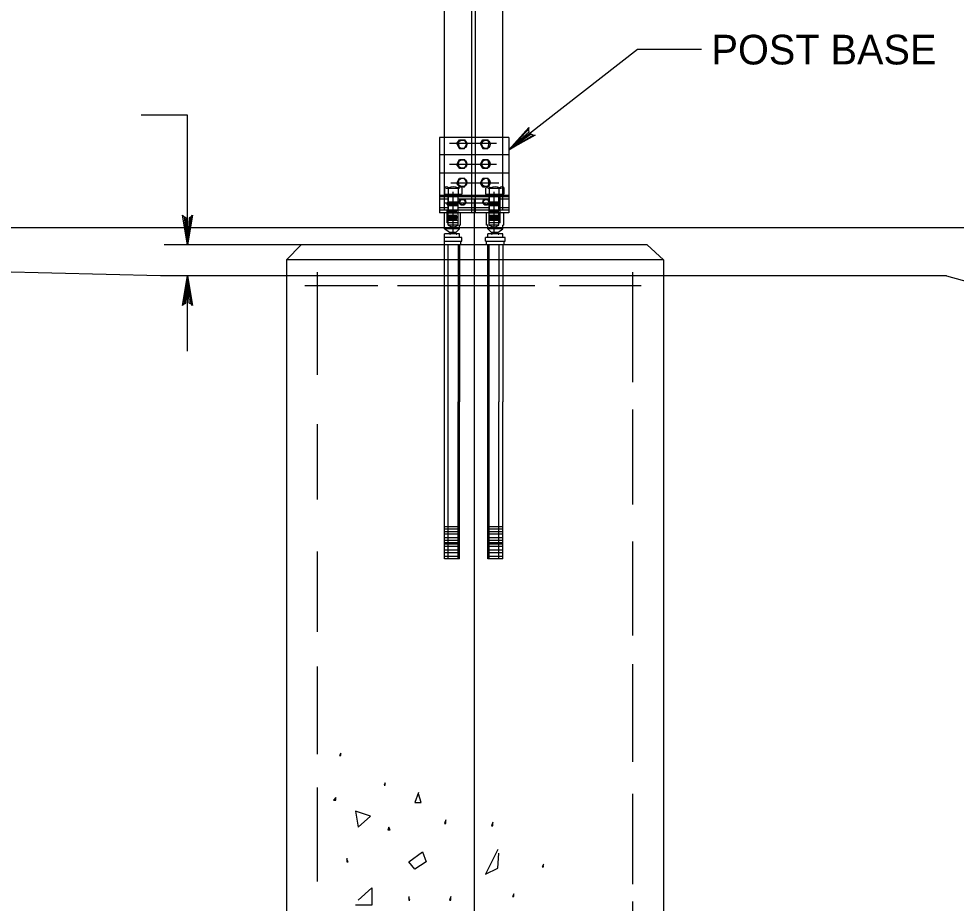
# Model space of a CAD drawing. Extents: x 637580 to 641008, y 294594 to 295782.
# Drawn here: x 637895.1 to 637989.9, y 295392.1 to 295481.5 of the extents above; entities that cross this region are included whole.
import ezdxf

# ---------------------------------------------------------------- set-up
doc = ezdxf.new("R2010")
doc.units = 0
for name, color, linetype in [('1', 7, 'Continuous'), ('2', 7, 'Continuous'), ('3', 7, 'Continuous')]:
    doc.layers.add(name, color=color, linetype=linetype)

# ---------------------------------------------------------------- blocks, each defined once
blk = doc.blocks.new('RARROW')
at = {"layer": '3'}
blk.add_lwpolyline([(-2.2695, 0.285), (-2.184875, 0.12075), (0, 0), (-2.2695, 0.285), (-2.38575, 0.384625), (0, 0), (-2.183125, -0.108), (-2.262875, -0.2705), (0, 0), (-2.38575, -0.379125), (-2.262875, -0.2705)], dxfattribs=at)

msp = doc.modelspace()

# ---------------------------------------------------------------- linework, layer by layer
at = {"layer": '2'}
for p, q in [((637940.937, 295461.876), (637940.937, 295676.876)), ((637941.312, 295461.876), (637941.312, 295676.876)), ((637938.187, 295469.501), (637938.187, 295549.501)), ((637944.062, 295469.501), (637944.062, 295549.501)), ((637957.687, 295478.376), (637944.687, 295468.236)), ((637964.187, 295478.376), (637957.687, 295478.376)), ((637912.187, 295471.751), (637907.499, 295471.751)), ((637912.187, 295458.626), (637912.187, 295471.751)), ((637944.687, 295469.501), (637937.687, 295469.501)), ((637937.687, 295469.501), (637937.687, 295462.126)), ((637938.187, 295462.126), (637938.187, 295469.501)), ((637939.437, 295468.876), (637939.687, 295469.251)), ((637939.562, 295468.876), (637939.687, 295469.251)), ((637939.687, 295469.251), (637940.187, 295469.251)), ((637939.687, 295469.251), (637940.187, 295469.251)), ((637940.187, 295469.251), (637940.437, 295468.876)), ((637940.437, 295468.876), (637940.187, 295469.251)), ((637941.812, 295468.876), (637942.062, 295469.251)), ((637941.812, 295468.876), (637942.062, 295469.251)), ((637942.062, 295469.251), (637942.562, 295469.251)), ((637942.062, 295469.251), (637942.562, 295469.251)), ((637942.562, 295469.251), (637942.687, 295468.876)), ((637942.687, 295468.876), (637942.562, 295469.251)), ((637944.062, 295462.126), (637944.062, 295469.501)), ((637944.687, 295469.501), (637944.687, 295462.126)), ((637943.437, 295468.876), (637938.687, 295468.876)), ((637939.687, 295468.376), (637939.437, 295468.876)), ((637939.562, 295468.876), (637939.687, 295468.376)), ((637939.687, 295468.376), (637940.187, 295468.376)), ((637939.687, 295468.376), (637940.187, 295468.376)), ((637939.937, 295468.876), (637939.937, 295468.876)), ((637939.937, 295468.876), (637939.937, 295468.876)), ((637939.937, 295468.876), (637939.937, 295468.876)), ((637940.187, 295468.376), (637940.437, 295468.876)), ((637940.187, 295468.376), (637940.437, 295468.876)), ((637941.812, 295468.876), (637942.062, 295468.376)), ((637942.062, 295468.376), (637941.812, 295468.876)), ((637942.062, 295468.376), (637942.562, 295468.376)), ((637942.062, 295468.376), (637942.562, 295468.376)), ((637942.312, 295468.876), (637942.312, 295468.876)), ((637942.312, 295468.876), (637942.312, 295468.876)), ((637942.312, 295468.876), (637942.312, 295468.876)), ((637942.562, 295468.376), (637942.687, 295468.876)), ((637942.562, 295468.376), (637942.687, 295468.876)), ((637944.687, 295467.751), (637937.687, 295467.751)), ((637943.437, 295466.751), (637938.687, 295466.751)), ((637939.437, 295466.751), (637939.687, 295467.251)), ((637939.687, 295466.376), (637939.437, 295466.751)), ((637939.562, 295466.751), (637939.687, 295467.251)), ((637939.562, 295466.751), (637939.687, 295466.376)), ((637939.687, 295467.251), (637940.187, 295467.251)), ((637939.687, 295467.251), (637940.187, 295467.251)), ((637939.937, 295466.751), (637939.937, 295466.751)), ((637939.937, 295466.751), (637939.937, 295466.751)), ((637939.937, 295466.751), (637939.937, 295466.751)), ((637940.187, 295467.251), (637940.437, 295466.751)), ((637940.437, 295466.751), (637940.187, 295467.251)), ((637940.187, 295466.376), (637940.437, 295466.751)), ((637940.187, 295466.376), (637940.437, 295466.751)), ((637941.812, 295466.751), (637942.062, 295467.251)), ((637941.812, 295466.751), (637942.062, 295467.251)), ((637941.812, 295466.751), (637942.062, 295466.376)), ((637942.062, 295466.376), (637941.812, 295466.751)), ((637942.062, 295467.251), (637942.562, 295467.251)), ((637942.062, 295467.251), (637942.562, 295467.251)), ((637942.312, 295466.751), (637942.312, 295466.751)), ((637942.312, 295466.751), (637942.312, 295466.751)), ((637942.312, 295466.751), (637942.312, 295466.751)), ((637942.562, 295467.251), (637942.687, 295466.751)), ((637942.687, 295466.751), (637942.562, 295467.251)), ((637942.562, 295466.376), (637942.687, 295466.751)), ((637942.562, 295466.376), (637942.687, 295466.751)), ((637944.687, 295465.876), (637937.687, 295465.876)), ((637939.687, 295466.376), (637940.187, 295466.376)), ((637939.687, 295466.376), (637940.187, 295466.376)), ((637942.062, 295466.376), (637942.562, 295466.376)), ((637942.062, 295466.376), (637942.562, 295466.376)), ((637943.687, 295464.876), (637938.812, 295464.876)), ((637939.437, 295464.876), (637939.687, 295465.376)), ((637939.687, 295464.501), (637939.437, 295464.876)), ((637939.562, 295464.876), (637939.687, 295465.376)), ((637939.562, 295464.876), (637939.687, 295464.501)), ((637939.687, 295465.376), (637940.187, 295465.376)), ((637939.687, 295465.376), (637940.187, 295465.376)), ((637939.687, 295464.501), (637940.187, 295464.501)), ((637939.687, 295464.501), (637940.187, 295464.501)), ((637939.937, 295464.876), (637939.937, 295464.876)), ((637939.937, 295464.876), (637939.937, 295464.876)), ((637939.937, 295464.876), (637939.937, 295464.876)), ((637940.187, 295465.376), (637940.437, 295464.876)), ((637940.437, 295464.876), (637940.187, 295465.376)), ((637940.187, 295464.501), (637940.437, 295464.876)), ((637940.187, 295464.501), (637940.437, 295464.876)), ((637941.812, 295464.876), (637942.062, 295465.376)), ((637941.812, 295464.876), (637942.062, 295465.376)), ((637941.812, 295464.876), (637942.062, 295464.501)), ((637942.062, 295464.501), (637941.812, 295464.876)), ((637942.062, 295465.376), (637942.562, 295465.376)), ((637942.062, 295465.376), (637942.562, 295465.376)), ((637942.062, 295464.501), (637942.562, 295464.501)), ((637942.062, 295464.501), (637942.562, 295464.501)), ((637942.312, 295464.876), (637942.312, 295464.876)), ((637942.312, 295464.876), (637942.312, 295464.876)), ((637942.312, 295464.876), (637942.312, 295464.876)), ((637942.562, 295465.376), (637942.687, 295464.876)), ((637942.687, 295464.876), (637942.562, 295465.376)), ((637942.562, 295464.501), (637942.687, 295464.876)), ((637942.562, 295464.501), (637942.687, 295464.876)), ((637938.562, 295463.626), (637937.687, 295463.626)), ((637938.187, 295464.376), (637938.187, 295464.376)), ((637938.187, 295464.376), (637938.187, 295463.751)), ((637938.187, 295463.751), (637939.937, 295463.751)), ((637938.187, 295463.626), (637938.187, 295463.751)), ((637938.187, 295463.626), (637939.687, 295463.626)), ((637938.312, 295464.376), (637938.312, 295464.376)), ((637938.312, 295464.376), (637938.562, 295464.376)), ((637938.562, 295464.376), (637938.562, 295463.751)), ((637938.562, 295464.376), (637939.562, 295464.376)), ((637938.562, 295464.376), (637938.562, 295464.376)), ((637938.562, 295463.001), (637938.562, 295463.751)), ((637938.562, 295463.626), (637938.562, 295461.876)), ((637939.062, 295464.376), (637939.062, 295464.376)), ((637939.062, 295460.001), (637939.062, 295464.001)), ((637939.062, 295463.626), (637939.062, 295463.626)), ((637939.062, 295463.626), (637939.062, 295463.626)), ((637939.562, 295464.376), (637939.562, 295463.751)), ((637939.562, 295464.376), (637939.562, 295464.376)), ((637939.562, 295464.376), (637939.687, 295464.376)), ((637939.562, 295463.001), (637939.562, 295463.751)), ((637939.562, 295461.876), (637939.562, 295463.626)), ((637942.687, 295463.626), (637939.562, 295463.626)), ((637939.687, 295464.376), (637939.687, 295464.376)), ((637939.687, 295463.626), (637939.812, 295463.751)), ((637939.937, 295464.376), (637939.937, 295464.376)), ((637939.937, 295464.376), (637939.937, 295463.751)), ((637942.312, 295464.376), (637942.312, 295464.376)), ((637942.312, 295464.376), (637942.312, 295463.751)), ((637942.312, 295463.751), (637944.187, 295463.751)), ((637942.437, 295463.626), (637942.437, 295463.751)), ((637942.437, 295463.626), (637944.062, 295463.626)), ((637942.562, 295464.376), (637942.562, 295464.376)), ((637942.562, 295464.376), (637942.687, 295464.376)), ((637942.687, 295464.376), (637942.687, 295463.751)), ((637942.687, 295464.376), (637943.687, 295464.376)), ((637942.687, 295464.376), (637942.687, 295464.376)), ((637942.687, 295463.001), (637942.687, 295463.751)), ((637942.687, 295463.626), (637942.687, 295461.876)), ((637943.187, 295464.376), (637943.187, 295464.376)), ((637943.187, 295460.001), (637943.187, 295464.001)), ((637943.187, 295463.626), (637943.187, 295463.626)), ((637943.187, 295463.626), (637943.187, 295463.626)), ((637943.687, 295464.376), (637943.687, 295463.751)), ((637943.687, 295464.376), (637943.687, 295464.376)), ((637943.687, 295464.376), (637943.937, 295464.376)), ((637943.687, 295463.001), (637943.687, 295463.751)), ((637943.812, 295461.876), (637943.812, 295463.626)), ((637944.687, 295463.626), (637943.812, 295463.626)), ((637943.937, 295464.376), (637943.937, 295464.376)), ((637944.062, 295463.626), (637944.062, 295463.751)), ((637944.187, 295464.376), (637944.187, 295464.376)), ((637944.187, 295464.376), (637944.187, 295463.751)), ((637944.687, 295463.501), (637937.687, 295463.501)), ((637938.562, 295463.251), (637937.687, 295463.251)), ((637938.187, 295462.876), (637943.562, 295462.876)), ((637938.437, 295462.876), (637938.562, 295463.001)), ((637938.437, 295462.876), (637939.562, 295462.876)), ((637938.437, 295462.751), (637938.437, 295462.876)), ((637938.437, 295462.751), (637939.562, 295462.751)), ((637938.562, 295462.626), (637938.437, 295462.751)), ((637938.562, 295463.001), (637939.562, 295463.001)), ((637938.562, 295462.126), (637938.562, 295462.626)), ((637938.562, 295462.626), (637939.562, 295462.626)), ((637939.062, 295462.876), (637939.062, 295462.876)), ((637942.687, 295463.251), (637939.562, 295463.251)), ((637939.562, 295462.876), (637939.562, 295463.001)), ((637939.562, 295462.751), (637939.562, 295462.876)), ((637939.562, 295462.626), (637939.562, 295462.751)), ((637939.562, 295462.126), (637939.562, 295462.626)), ((637939.937, 295462.876), (637939.937, 295462.876)), ((637941.187, 295463.251), (637941.187, 295379.001)), ((637942.312, 295462.876), (637942.312, 295462.876)), ((637942.687, 295462.876), (637942.687, 295463.001)), ((637942.687, 295463.001), (637943.687, 295463.001)), ((637942.687, 295462.876), (637943.812, 295462.876)), ((637942.687, 295462.751), (637942.687, 295462.876)), ((637942.687, 295462.751), (637943.812, 295462.751)), ((637942.687, 295462.626), (637942.687, 295462.751)), ((637942.687, 295462.126), (637942.687, 295462.626)), ((637942.687, 295462.626), (637943.687, 295462.626)), ((637943.187, 295462.876), (637943.187, 295462.876)), ((637943.812, 295462.876), (637943.687, 295463.001)), ((637943.687, 295462.626), (637943.812, 295462.751)), ((637943.687, 295462.126), (637943.687, 295462.626)), ((637944.687, 295463.251), (637943.812, 295463.251)), ((637943.812, 295462.751), (637943.812, 295462.876)), ((637938.562, 295462.376), (637937.687, 295462.376)), ((637944.687, 295462.126), (637937.687, 295462.126)), ((637937.687, 295462.126), (637937.687, 295461.876)), ((637944.312, 295461.876), (637937.687, 295461.876)), ((637938.562, 295461.876), (637937.687, 295461.876)), ((637938.187, 295460.626), (637938.187, 295461.876)), ((637939.812, 295461.876), (637938.187, 295461.876)), ((637938.437, 295462.126), (637939.562, 295462.126)), ((637938.437, 295461.126), (637938.437, 295462.126)), ((637938.437, 295460.876), (637938.437, 295461.876)), ((637938.437, 295461.876), (637939.562, 295461.876)), ((637938.562, 295462.001), (637939.437, 295462.001)), ((637938.562, 295460.626), (637938.562, 295461.876)), ((637939.062, 295461.876), (637939.062, 295461.876)), ((637939.062, 295461.876), (637939.062, 295461.876)), ((637942.687, 295462.376), (637939.562, 295462.376)), ((637939.562, 295461.126), (637939.562, 295462.126)), ((637942.687, 295461.876), (637939.562, 295461.876)), ((637939.562, 295460.876), (637939.562, 295461.876)), ((637939.562, 295460.626), (637939.562, 295461.876)), ((637939.812, 295460.626), (637939.812, 295461.876)), ((637941.187, 295462.126), (637941.187, 295462.126)), ((637941.187, 295461.876), (637941.187, 295461.876)), ((637941.187, 295461.876), (637941.187, 295461.876)), ((637942.437, 295460.626), (637942.437, 295461.876)), ((637944.187, 295461.876), (637942.437, 295461.876)), ((637942.687, 295462.126), (637943.812, 295462.126)), ((637942.687, 295461.126), (637942.687, 295462.126)), ((637942.687, 295462.001), (637943.687, 295462.001)), ((637942.687, 295460.876), (637942.687, 295461.876)), ((637942.687, 295460.626), (637942.687, 295461.876)), ((637942.687, 295461.876), (637943.812, 295461.876)), ((637943.187, 295461.876), (637943.187, 295461.876)), ((637943.187, 295461.876), (637943.187, 295461.876)), ((637943.687, 295460.626), (637943.687, 295461.876)), ((637944.687, 295462.376), (637943.812, 295462.376)), ((637943.812, 295461.126), (637943.812, 295462.126)), ((637944.687, 295461.876), (637943.812, 295461.876)), ((637943.812, 295460.876), (637943.812, 295461.876)), ((637944.187, 295460.626), (637944.187, 295461.876)), ((637944.687, 295462.126), (637944.687, 295461.876)), ((637938.437, 295461.501), (637939.562, 295461.501)), ((637938.437, 295461.376), (637939.562, 295461.376)), ((637938.437, 295461.126), (637939.562, 295461.126)), ((637939.562, 295460.876), (637938.437, 295460.876)), ((637938.562, 295461.626), (637939.437, 295461.626)), ((637938.562, 295461.376), (637939.437, 295461.376)), ((637938.562, 295461.251), (637939.437, 295461.251)), ((637939.062, 295461.126), (637939.062, 295461.126)), ((637942.687, 295461.626), (637943.687, 295461.626)), ((637942.687, 295461.501), (637943.812, 295461.501)), ((637942.687, 295461.376), (637943.812, 295461.376)), ((637942.687, 295461.376), (637943.687, 295461.376)), ((637942.687, 295461.251), (637943.687, 295461.251)), ((637942.687, 295461.126), (637943.812, 295461.126)), ((637943.812, 295460.876), (637942.687, 295460.876)), ((637943.187, 295461.126), (637943.187, 295461.126)), ((637909.437, 295455.501), (637719.187, 295460.376)), ((637724.687, 295460.376), (638231.687, 295460.376)), ((637938.187, 295460.251), (637938.187, 295460.626)), ((637938.187, 295460.626), (637938.187, 295460.626)), ((637938.687, 295459.876), (637938.187, 295460.251)), ((637939.687, 295460.251), (637938.187, 295460.251)), ((637939.562, 295460.626), (637938.562, 295460.626)), ((637938.562, 295460.626), (637939.062, 295460.376)), ((637938.687, 295459.876), (637938.687, 295459.876)), ((637939.312, 295459.876), (637938.687, 295459.876)), ((637939.062, 295460.376), (637939.562, 295460.626)), ((637939.062, 295460.376), (637939.062, 295460.376)), ((637939.312, 295459.876), (637939.687, 295460.251)), ((637939.312, 295459.876), (637939.312, 295459.876)), ((637939.687, 295460.251), (637939.687, 295460.626)), ((637939.812, 295460.626), (637939.687, 295460.626)), ((637941.187, 295460.376), (637941.187, 295460.376)), ((637942.562, 295460.626), (637942.437, 295460.626)), ((637942.562, 295460.251), (637942.562, 295460.626)), ((637942.937, 295459.876), (637942.562, 295460.251)), ((637944.062, 295460.251), (637942.562, 295460.251)), ((637943.687, 295460.626), (637942.687, 295460.626)), ((637942.687, 295460.626), (637943.187, 295460.376)), ((637942.937, 295459.876), (637942.937, 295459.876)), ((637943.562, 295459.876), (637942.937, 295459.876)), ((637943.187, 295460.376), (637943.687, 295460.626)), ((637943.187, 295460.376), (637943.187, 295460.376)), ((637943.562, 295459.876), (637944.062, 295460.251)), ((637943.562, 295459.876), (637943.562, 295459.876)), ((637944.062, 295460.251), (637944.062, 295460.626)), ((637944.187, 295460.626), (637944.062, 295460.626)), ((637938.187, 295459.376), (637938.187, 295459.751)), ((637939.687, 295459.751), (637938.187, 295459.751)), ((637939.937, 295459.376), (637938.187, 295459.376)), ((637938.187, 295459.001), (637938.187, 295459.376)), ((637938.187, 295459.001), (637939.937, 295459.001)), ((637938.187, 295458.626), (637938.187, 295459.001)), ((637939.062, 295459.376), (637939.062, 295459.376)), ((637939.687, 295459.376), (637939.687, 295459.751)), ((637939.812, 295459.001), (637939.812, 295458.626)), ((637939.937, 295459.001), (637939.937, 295459.376)), ((637944.312, 295459.376), (637942.312, 295459.376)), ((637942.312, 295459.001), (637942.312, 295459.376)), ((637942.312, 295459.001), (637944.312, 295459.001)), ((637942.437, 295458.626), (637942.437, 295459.001)), ((637942.562, 295459.376), (637942.562, 295459.751)), ((637944.062, 295459.751), (637942.562, 295459.751)), ((637943.187, 295459.376), (637943.187, 295459.376)), ((637944.062, 295459.376), (637944.062, 295459.751)), ((637944.187, 295459.001), (637944.187, 295458.626)), ((637944.312, 295459.001), (637944.312, 295459.376)), ((637923.687, 295458.626), (637909.812, 295458.626)), ((637922.187, 295457.126), (637923.687, 295458.626)), ((637958.687, 295458.626), (637923.687, 295458.626)), ((637938.187, 295442.751), (637938.187, 295458.626)), ((637938.562, 295442.751), (637938.562, 295458.626)), ((637939.062, 295458.626), (637939.062, 295458.626)), ((637939.562, 295458.626), (637939.562, 295442.751)), ((637939.687, 295458.626), (637939.687, 295442.751)), ((637941.187, 295458.626), (637941.187, 295458.626)), ((637941.187, 295458.626), (637941.187, 295458.626)), ((637942.562, 295442.751), (637942.562, 295458.626)), ((637942.687, 295442.751), (637942.687, 295458.626)), ((637943.187, 295458.626), (637943.187, 295458.626)), ((637943.687, 295458.626), (637943.687, 295442.751)), ((637944.062, 295458.626), (637944.062, 295442.751)), ((637958.687, 295458.626), (637958.062, 295458.626)), ((637958.687, 295458.626), (637960.312, 295457.126)), ((637960.312, 295457.126), (637922.187, 295457.126)), ((637922.187, 295457.126), (637922.187, 295454.751)), ((637960.312, 295457.126), (637960.312, 295454.126)), ((637988.937, 295455.501), (637909.437, 295455.501)), ((637912.187, 295447.876), (637912.187, 295455.501)), ((637925.312, 295455.876), (637925.312, 295445.501)), ((637957.187, 295455.876), (637957.187, 295444.751)), ((637988.937, 295455.501), (638183.937, 295401.376)), ((637922.187, 295454.751), (637922.187, 295382.376)), ((637931.437, 295454.501), (637924.062, 295454.501)), ((637947.312, 295454.501), (637933.437, 295454.501)), ((637958.062, 295454.501), (637949.812, 295454.501)), ((637960.312, 295454.126), (637960.312, 295382.376)), ((637938.187, 295426.876), (637938.187, 295442.751)), ((637938.562, 295426.876), (637938.562, 295442.751)), ((637939.562, 295426.876), (637939.562, 295442.751)), ((637939.687, 295426.876), (637939.687, 295442.751)), ((637942.562, 295426.876), (637942.562, 295442.751)), ((637942.687, 295426.876), (637942.687, 295442.751)), ((637943.687, 295426.876), (637943.687, 295442.751)), ((637944.062, 295426.876), (637944.062, 295442.751)), ((637957.187, 295442.001), (637957.187, 295432.376)), ((637925.312, 295440.501), (637925.312, 295432.876)), ((637939.687, 295430.126), (637938.187, 295430.126)), ((637939.687, 295429.876), (637938.187, 295429.876)), ((637939.687, 295429.626), (637938.187, 295429.626)), ((637944.062, 295430.126), (637942.562, 295430.126)), ((637944.062, 295429.876), (637942.562, 295429.876)), ((637944.062, 295429.626), (637942.562, 295429.626)), ((637939.687, 295429.376), (637938.187, 295429.376)), ((637939.687, 295429.001), (637938.187, 295429.001)), ((637939.687, 295428.751), (637938.187, 295428.751)), ((637939.687, 295428.501), (637938.187, 295428.501)), ((637944.062, 295429.376), (637942.562, 295429.376)), ((637944.062, 295429.001), (637942.562, 295429.001)), ((637944.062, 295428.751), (637942.562, 295428.751)), ((637944.062, 295428.501), (637942.562, 295428.501)), ((637957.187, 295428.626), (637957.187, 295419.126)), ((637925.312, 295427.626), (637925.312, 295419.501)), ((637939.687, 295428.376), (637938.187, 295428.376)), ((637939.687, 295428.126), (637938.187, 295428.126)), ((637939.687, 295427.751), (637938.187, 295427.751)), ((637944.062, 295428.376), (637942.562, 295428.376)), ((637944.062, 295428.126), (637942.562, 295428.126)), ((637944.062, 295427.751), (637942.562, 295427.751)), ((637939.687, 295427.501), (637938.187, 295427.501)), ((637939.687, 295427.126), (637938.187, 295427.126)), ((637939.687, 295426.876), (637938.187, 295426.876)), ((637944.062, 295427.501), (637942.562, 295427.501)), ((637944.062, 295427.126), (637942.562, 295427.126)), ((637944.062, 295426.876), (637942.562, 295426.876)), ((637957.187, 295416.251), (637957.187, 295406.376)), ((637925.312, 295416.001), (637925.312, 295407.126)), ((637925.312, 295403.751), (637925.312, 295394.251)), ((637957.187, 295403.126), (637957.187, 295394.001)), ((637957.187, 295392.251), (637957.187, 295385.251))]:
    msp.add_line(p, q, dxfattribs=at)
for points in [[(637927.687, 295407.251), (637927.562, 295407.001), (637927.687, 295407.001), (637927.687, 295407.251)], [(637932.187, 295404.251), (637932.062, 295404.001), (637932.187, 295404.001), (637932.187, 295404.251)], [(637935.562, 295403.251), (637935.187, 295402.251), (637935.812, 295402.251), (637935.562, 295403.126)], [(637927.187, 295402.751), (637926.937, 295402.501), (637927.187, 295402.501), (637927.187, 295402.751)], [(637929.187, 295401.376), (637929.437, 295399.751), (637930.687, 295400.876), (637929.187, 295401.376)], [(637938.312, 295400.501), (637938.187, 295400.126), (637938.312, 295400.126), (637938.312, 295400.376)], [(637943.062, 295400.251), (637942.937, 295399.876), (637943.062, 295399.876), (637943.062, 295400.126)], [(637932.562, 295399.751), (637932.437, 295399.501), (637932.687, 295399.501), (637932.562, 295399.751)], [(637934.562, 295396.251), (637935.937, 295397.251), (637936.312, 295396.251), (637935.187, 295395.501), (637934.562, 295396.251)], [(637943.562, 295397.501), (637942.312, 295395.001), (637943.562, 295395.626), (637943.687, 295397.126)], [(637928.312, 295396.626), (637928.312, 295396.251), (637928.437, 295396.251), (637928.312, 295396.501)], [(637948.187, 295396.001), (637948.062, 295395.751), (637948.187, 295395.751), (637948.187, 295395.876)], [(637929.437, 295392.376), (637930.812, 295393.626), (637930.812, 295391.876), (637929.187, 295391.876)], [(637934.562, 295392.751), (637934.562, 295392.376), (637934.687, 295392.376), (637934.562, 295392.626)], [(637938.812, 295392.751), (637938.687, 295392.376), (637938.812, 295392.376), (637938.812, 295392.626)], [(637945.187, 295393.001), (637945.062, 295392.751), (637945.187, 295392.751), (637945.187, 295393.001)]]:
    msp.add_lwpolyline(points, dxfattribs=at)
for centre, major_axis in [((637940, 295468.799), (0, 0.432)), ((637940, 295468.799), (0, -0.432)), ((637942.381, 295468.799), (0, 0.432)), ((637942.381, 295468.799), (0, -0.432)), ((637940, 295466.809), (0, 0.432)), ((637940, 295466.809), (0, -0.432)), ((637942.381, 295466.809), (0, 0.432)), ((637942.381, 295466.809), (0, -0.432)), ((637940, 295464.953), (0, 0.432)), ((637940, 295464.953), (0, -0.432)), ((637942.381, 295464.953), (0, 0.432)), ((637942.381, 295464.953), (0, -0.432)), ((637940.001, 295462.963), (0, 0.331)), ((637940.001, 295462.963), (0, 0.265)), ((637942.381, 295462.963), (0, 0.331)), ((637942.381, 295462.963), (0, 0.265))]:
    msp.add_ellipse(centre, major_axis=major_axis, ratio=0.996388, dxfattribs=at)
for centre, major_axis, start_param, end_param in [((637938.391, 295464.248), (0, -0.259), 2.218404, 4.064781), ((637939.074, 295463.341), (0, -1.166), 2.718335, 3.56485), ((637939.76, 295464.243), (0, -0.265), 2.228521, 4.054665), ((637942.618, 295464.248), (0, -0.259), 2.218404, 4.064781), ((637943.302, 295463.341), (0, -1.166), 2.718335, 3.56485), ((637943.988, 295464.243), (0, -0.265), 2.228521, 4.054665), ((637938.549, 295462.22), (0, 0.0993), 3.141593, 4.712389), ((637939.605, 295462.22), (0, -0.0993), 4.712389, 6.283185), ((637942.776, 295462.22), (0, 0.0993), 3.141593, 4.712389), ((637943.832, 295462.22), (0, -0.0993), 4.712389, 6.283185), ((637938.714, 295459.778), (0, 0.0662), 3.141593, 4.712389), ((637939.44, 295459.778), (0, -0.0662), 4.712389, 6.283185), ((637942.941, 295459.778), (0, 0.0662), 3.141593, 4.712389), ((637943.667, 295459.778), (0, -0.0662), 4.712389, 6.283185)]:
    msp.add_ellipse(centre, major_axis=major_axis, ratio=0.996388, start_param=start_param, end_param=end_param, dxfattribs=at)

# ---------------------------------------------------------------- block references
at = {"layer": '2', "xscale": 1.2574347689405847}
for p, yscale, rotation in [((637944.687, 295468.236), 1.3092961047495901, -141.2085354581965), ((637912.187, 295458.626), 1.3092961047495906, -90.00000000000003), ((637912.187, 295455.501), 1.3092961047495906, 89.99999999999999)]:
    msp.add_blockref('RARROW', p, dxfattribs=dict(at, yscale=yscale, rotation=rotation))

# ---------------------------------------------------------------- texts
at = {"layer": '1'}
msp.add_text('POST BASE', height=3, dxfattribs=at).set_placement((637965.187, 295476.876))

doc.saveas('drawing.dxf')
